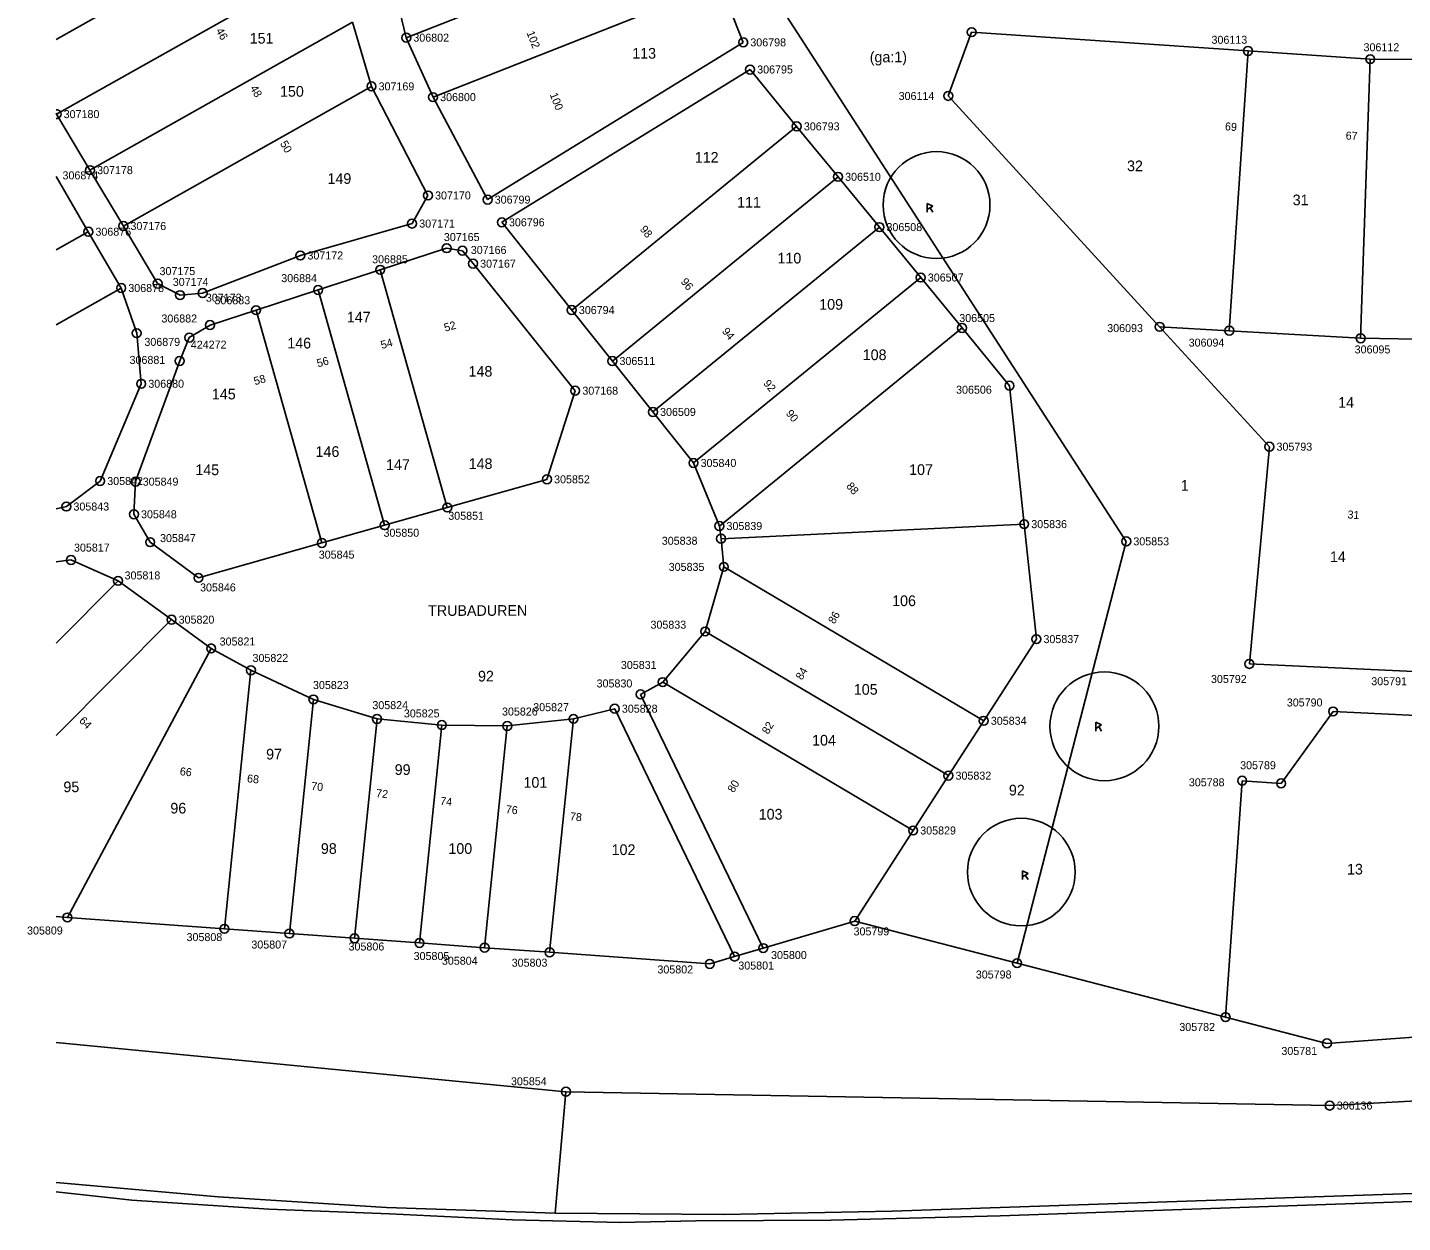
# Model space of a CAD drawing. Extents: x 141995 to 152570, y 6580184 to 6586000.
# Drawn here: x 141996.8 to 142151.4, y 6585355.2 to 6585489.6 of the extents above; entities that cross this region are included whole.
import ezdxf

# ---------------------------------------------------------------- set-up
doc = ezdxf.new("R2010")
doc.units = 0
for name, color, linetype in [('Level 10', 7, 'Continuous'), ('Level 12', 7, 'Continuous'), ('Level 13', 7, 'Continuous'), ('Level 5', 7, 'Continuous'), ('Level 51', 7, 'Continuous'), ('Level 53', 7, 'Continuous'), ('Level 54', 7, 'Continuous'), ('Level 58', 7, 'Continuous'), ('Level 59', 7, 'Continuous'), ('Level 6', 7, 'Continuous'), ('Level 7', 7, 'Continuous')]:
    doc.layers.add(name, color=color, linetype=linetype)

msp = doc.modelspace()

# ---------------------------------------------------------------- linework, layer by layer
at = {"layer": 'Level 10'}
for centre in [(142039.39, 6585488.48), (142077.29, 6585487.95), (142102.98, 6585489.1), (142134.07, 6585486.99), (142078.06, 6585484.89), (142147.81, 6585486.06), (142035.48, 6585483), (142042.4, 6585481.79), (142100.35, 6585481.93), (142083.3, 6585478.5), (142003.81, 6585473.58), (142087.95, 6585472.83), (142041.83, 6585470.73), (142048.54, 6585470.26), (142003.63, 6585466.65), (142007.57, 6585467.29), (142040.04, 6585467.57), (142050.14, 6585467.71), (142092.6, 6585467.17), (142043.93, 6585464.8), (142027.48, 6585463.98), (142045.71, 6585464.52), (142036.46, 6585462.37), (142046.9, 6585463.06), (142007.33, 6585460.32), (142011.43, 6585460.82), (142029.48, 6585460.1), (142097.25, 6585461.5), (142013.95, 6585459.52), (142016.49, 6585459.75), (142022.5, 6585457.83), (142058, 6585457.84), (142017.32, 6585456.15), (142101.9, 6585455.83), (142124.12, 6585455.96), (142131.96, 6585455.52), (142009.07, 6585455.24), (142014.99, 6585454.74), (142146.73, 6585454.67), (142013.91, 6585452.12), (142062.57, 6585452.11), (142009.58, 6585449.55), (142107.24, 6585449.33), (142058.39, 6585448.77), (142067.14, 6585446.38), (142136.47, 6585442.47), (142071.7, 6585440.64), (142004.96, 6585438.61), (142008.95, 6585438.54), (142055.22, 6585438.8), (142001.16, 6585435.74), (142044.01, 6585435.63), (142008.76, 6585434.87), (142108.89, 6585433.76), (142036.96, 6585433.64), (142074.61, 6585433.55), (142010.59, 6585431.73), (142029.9, 6585431.64), (142074.8, 6585432.12), (142120.37, 6585431.82), (142001.68, 6585429.73), (142016.02, 6585427.72), (142075.11, 6585428.96), (142006.98, 6585427.38), (142012.99, 6585423.02), (142073.01, 6585421.69), (142110.26, 6585420.82), (142017.45, 6585419.78), (142021.92, 6585417.32), (142134.22, 6585418.04), (142068.24, 6585415.99), (142028.95, 6585414.04), (142065.74, 6585414.61), (142062.84, 6585413), (142143.64, 6585412.69), (142036.1, 6585411.85), (142043.39, 6585411.16), (142050.75, 6585411.06), (142058.2, 6585411.86), (142104.34, 6585411.64), (142100.37, 6585405.47), (142133.41, 6585404.9), (142137.79, 6585404.6), (142096.4, 6585399.3), (142001.28, 6585389.52), (142089.83, 6585389.11), (142018.94, 6585388.24), (142026.25, 6585387.71), (142033.57, 6585387.18), (142040.88, 6585386.65), (142048.2, 6585386.12), (142079.54, 6585386.07), (142055.51, 6585385.6), (142073.53, 6585384.29), (142076.32, 6585385.12), (142108.09, 6585384.38), (142131.54, 6585378.31), (142142.94, 6585375.36), (142057.35, 6585369.92), (142143.25, 6585368.36)]:
    msp.add_circle(centre, 0.5, dxfattribs=at)
msp.add_arc((142000.06, 6585479.88), 0.5, 263.4159, 96.5841, dxfattribs=at)
at = {"layer": 'Level 12'}
for p, q in [((142097.98, 6585468.84), (142097.98, 6585469.84)), ((142097.98, 6585469.84), (142098.63, 6585469.54)), ((142098.63, 6585469.54), (142097.98, 6585469.14)), ((142098.31, 6585469.34), (142098.63, 6585468.84)), ((142116.94, 6585410.48), (142116.94, 6585411.48)), ((142116.94, 6585411.48), (142117.59, 6585411.18)), ((142117.59, 6585411.18), (142116.94, 6585410.78)), ((142117.27, 6585410.98), (142117.59, 6585410.48)), ((142108.69, 6585393.78), (142108.69, 6585394.78)), ((142108.69, 6585394.78), (142109.34, 6585394.48)), ((142109.34, 6585394.48), (142108.69, 6585394.08)), ((142109.01, 6585394.28), (142109.34, 6585393.78))]:
    msp.add_line(p, q, dxfattribs=at)
for centre, radius in [((142099.03, 6585469.65), 6.01), ((142117.91, 6585411.02), 6.12), ((142108.57, 6585394.62), 6.05)]:
    msp.add_circle(centre, radius, dxfattribs=at)
at = {"layer": 'Level 13'}
for points in [[(142106.18, 6585355.96), (142199.95, 6585359.22), (142280.34, 6585361.53), (142298.3, 6585362.96), (142308.55, 6585364.2), (142315.26, 6585364.94), (142322.71, 6585365.48), (142328.56, 6585365.72), (142332.32, 6585365.37), (142336.72, 6585364.61), (142340.97, 6585363.81), (142343.67, 6585363.75), (142345.72, 6585364.6), (142347.07, 6585365.5), (142347.87, 6585367.45), (142347.76, 6585371.19)], [(142000, 6585358.67), (142008.52, 6585357.72), (142023.93, 6585356.72), (142037.52, 6585356.17), (142051.35, 6585355.52), (142063.46, 6585355.21), (142071.96, 6585355.38), (142087.17, 6585355.46), (142106.18, 6585355.96)]]:
    msp.add_lwpolyline(points, dxfattribs=at)
at = {"layer": 'Level 5'}
for points in [[(142001.28, 6585389.52), (142000, 6585389.61)], [(142018.94, 6585388.24), (142001.28, 6585389.52)], [(142026.25, 6585387.71), (142018.94, 6585388.24)], [(142089.83, 6585389.11), (142079.54, 6585386.07)], [(142108.09, 6585384.38), (142089.83, 6585389.11)], [(142033.57, 6585387.18), (142026.25, 6585387.71)], [(142040.88, 6585386.65), (142033.57, 6585387.18)], [(142048.2, 6585386.12), (142040.88, 6585386.65)], [(142055.51, 6585385.6), (142048.2, 6585386.12)], [(142073.53, 6585384.29), (142055.51, 6585385.6)], [(142076.32, 6585385.12), (142073.53, 6585384.29)], [(142079.54, 6585386.07), (142076.32, 6585385.12)], [(142108.09, 6585384.38), (142131.54, 6585378.31)], [(142142.94, 6585375.36), (142131.54, 6585378.31)], [(142156.85, 6585376.35), (142142.94, 6585375.36)], [(142143.25, 6585368.36), (142295.25, 6585376.5)], [(142000, 6585375.45), (142057.35, 6585369.92)], [(142057.35, 6585369.92), (142143.25, 6585368.36)], [(142094.06, 6585356.49), (142340.21, 6585364.86)], [(142018.24, 6585358.08), (142000, 6585359.72)], [(142037.17, 6585356.91), (142018.24, 6585358.08)], [(142056.13, 6585356.25), (142037.17, 6585356.91)], [(142075.1, 6585356.11), (142056.13, 6585356.25)], [(142094.06, 6585356.49), (142075.1, 6585356.11)]]:
    msp.add_lwpolyline(points, dxfattribs=at)
at = {"layer": 'Level 6'}
msp.add_lwpolyline([(142000, 6585389.61), (142001.28, 6585389.52), (142018.94, 6585388.24), (142026.25, 6585387.71), (142033.57, 6585387.18), (142040.88, 6585386.65), (142048.2, 6585386.12), (142055.51, 6585385.6), (142073.53, 6585384.29), (142076.32, 6585385.12), (142079.54, 6585386.07), (142089.83, 6585389.11), (142108.09, 6585384.38), (142131.54, 6585378.31), (142142.94, 6585375.36), (142156.85, 6585376.35)], dxfattribs=at)
at = {"layer": 'Level 7'}
for points in [[(142066.65, 6585514.98), (142120.37, 6585431.82)], [(142000, 6585488.26), (142028.3, 6585504.2)], [(142039.39, 6585488.48), (142072.02, 6585501.34)], [(142000.06, 6585479.88), (142031.24, 6585497.44)], [(142037.64, 6585495.67), (142039.39, 6585488.48)], [(142042.4, 6585481.79), (142074.71, 6585494.52)], [(142077.29, 6585487.95), (142074.71, 6585494.52)], [(142003.81, 6585473.58), (142033.36, 6585490.22)], [(142033.36, 6585490.22), (142035.48, 6585483)], [(142039.39, 6585488.48), (142042.4, 6585481.79)], [(142100.35, 6585481.93), (142102.98, 6585489.1)], [(142102.98, 6585489.1), (142134.07, 6585486.99)], [(142048.54, 6585470.26), (142077.29, 6585487.95)], [(142131.96, 6585455.52), (142134.07, 6585486.99)], [(142134.07, 6585486.99), (142147.81, 6585486.06)], [(142146.73, 6585454.67), (142147.81, 6585486.06)], [(142147.81, 6585486.06), (142161.52, 6585485.99)], [(142078.06, 6585484.89), (142050.14, 6585467.71)], [(142083.3, 6585478.5), (142078.06, 6585484.89)], [(142007.57, 6585467.29), (142035.48, 6585483)], [(142035.48, 6585483), (142041.83, 6585470.73)], [(142042.4, 6585481.79), (142048.54, 6585470.26)], [(142124.12, 6585455.96), (142100.35, 6585481.93)], [(142000.06, 6585479.88), (142000, 6585479.98)], [(142003.81, 6585473.58), (142000.06, 6585479.88)], [(142058, 6585457.84), (142083.3, 6585478.5)], [(142087.95, 6585472.83), (142083.3, 6585478.5)], [(142007.57, 6585467.29), (142003.81, 6585473.58)], [(142000, 6585472.87), (142003.63, 6585466.65)], [(142062.57, 6585452.11), (142087.95, 6585472.83)], [(142092.6, 6585467.17), (142087.95, 6585472.83)], [(142041.83, 6585470.73), (142040.04, 6585467.57)], [(142011.43, 6585460.82), (142007.57, 6585467.29)], [(142040.04, 6585467.57), (142027.48, 6585463.98)], [(142050.14, 6585467.71), (142058, 6585457.84)], [(142067.14, 6585446.38), (142092.6, 6585467.17)], [(142092.6, 6585467.17), (142097.25, 6585461.5)], [(142003.63, 6585466.65), (142000, 6585464.6)], [(142003.63, 6585466.65), (142007.33, 6585460.32)], [(142027.48, 6585463.98), (142016.49, 6585459.75)], [(142036.46, 6585462.37), (142043.93, 6585464.8)], [(142043.93, 6585464.8), (142045.71, 6585464.52)], [(142045.71, 6585464.52), (142046.9, 6585463.06)], [(142029.48, 6585460.1), (142036.46, 6585462.37)], [(142036.46, 6585462.37), (142044.01, 6585435.63)], [(142046.9, 6585463.06), (142058.39, 6585448.77)], [(142013.95, 6585459.52), (142011.43, 6585460.82)], [(142097.25, 6585461.5), (142071.7, 6585440.64)], [(142101.9, 6585455.83), (142097.25, 6585461.5)], [(142007.33, 6585460.32), (142000, 6585456.18)], [(142007.33, 6585460.32), (142009.07, 6585455.24)], [(142016.49, 6585459.75), (142013.95, 6585459.52)], [(142022.5, 6585457.83), (142029.48, 6585460.1)], [(142029.48, 6585460.1), (142036.96, 6585433.64)], [(142017.32, 6585456.15), (142022.5, 6585457.83)], [(142022.5, 6585457.83), (142029.9, 6585431.64)], [(142058, 6585457.84), (142062.57, 6585452.11)], [(142014.99, 6585454.74), (142017.32, 6585456.15)], [(142124.12, 6585455.96), (142131.96, 6585455.52)], [(142124.12, 6585455.96), (142136.47, 6585442.47)], [(142009.07, 6585455.24), (142009.58, 6585449.55)], [(142013.91, 6585452.12), (142014.99, 6585454.74)], [(142101.9, 6585455.83), (142074.61, 6585433.55)], [(142101.9, 6585455.83), (142107.24, 6585449.33)], [(142131.96, 6585455.52), (142146.73, 6585454.67)], [(142146.73, 6585454.67), (142155.21, 6585454.53)], [(142013.91, 6585452.12), (142008.95, 6585438.54)], [(142062.57, 6585452.11), (142067.14, 6585446.38)], [(142009.58, 6585449.55), (142004.96, 6585438.61)], [(142058.39, 6585448.77), (142055.22, 6585438.8)], [(142107.24, 6585449.33), (142108.89, 6585433.76)], [(142067.14, 6585446.38), (142071.7, 6585440.64)], [(142134.22, 6585418.04), (142136.47, 6585442.47)], [(142071.7, 6585440.64), (142074.61, 6585433.55)], [(142004.96, 6585438.61), (142001.16, 6585435.74)], [(142008.76, 6585434.87), (142008.95, 6585438.54)], [(142055.22, 6585438.8), (142044.01, 6585435.63)], [(142001.16, 6585435.74), (142000, 6585435.47)], [(142010.59, 6585431.73), (142008.76, 6585434.87)], [(142044.01, 6585435.63), (142036.96, 6585433.64)], [(142036.96, 6585433.64), (142029.9, 6585431.64)], [(142074.8, 6585432.12), (142074.61, 6585433.55)], [(142108.89, 6585433.76), (142074.8, 6585432.12)], [(142110.26, 6585420.82), (142108.89, 6585433.76)], [(142016.02, 6585427.72), (142010.59, 6585431.73)], [(142029.9, 6585431.64), (142016.02, 6585427.72)], [(142074.8, 6585432.12), (142075.11, 6585428.96)], [(142120.37, 6585431.82), (142108.09, 6585384.38)], [(142001.68, 6585429.73), (142000, 6585429.52)], [(142006.98, 6585427.38), (142001.68, 6585429.73)], [(142075.11, 6585428.96), (142073.01, 6585421.69)], [(142075.11, 6585428.96), (142104.34, 6585411.64)], [(142006.98, 6585427.38), (142000, 6585420.38)], [(142012.99, 6585423.02), (142006.98, 6585427.38)], [(142012.99, 6585423.02), (142000, 6585410)], [(142017.45, 6585419.78), (142012.99, 6585423.02)], [(142073.01, 6585421.69), (142068.24, 6585415.99)], [(142073.01, 6585421.69), (142100.37, 6585405.47)], [(142104.34, 6585411.64), (142110.26, 6585420.82)], [(142017.45, 6585419.78), (142001.28, 6585389.52)], [(142021.92, 6585417.32), (142017.45, 6585419.78)], [(142021.92, 6585417.32), (142018.94, 6585388.24)], [(142028.95, 6585414.04), (142021.92, 6585417.32)], [(142152.7, 6585417.19), (142134.22, 6585418.04)], [(142068.24, 6585415.99), (142065.74, 6585414.61)], [(142068.24, 6585415.99), (142096.4, 6585399.3)], [(142065.74, 6585414.61), (142079.54, 6585386.07)], [(142028.95, 6585414.04), (142026.25, 6585387.71)], [(142036.1, 6585411.85), (142028.95, 6585414.04)], [(142062.84, 6585413), (142058.2, 6585411.86)], [(142076.32, 6585385.12), (142062.84, 6585413)], [(142137.79, 6585404.6), (142143.64, 6585412.69)], [(142143.64, 6585412.69), (142159.2, 6585411.93)], [(142036.1, 6585411.85), (142033.57, 6585387.18)], [(142043.39, 6585411.16), (142036.1, 6585411.85)], [(142043.39, 6585411.16), (142040.88, 6585386.65)], [(142050.75, 6585411.06), (142043.39, 6585411.16)], [(142050.75, 6585411.06), (142048.2, 6585386.12)], [(142058.2, 6585411.86), (142050.75, 6585411.06)], [(142058.2, 6585411.86), (142055.51, 6585385.6)], [(142100.37, 6585405.47), (142104.34, 6585411.64)], [(142096.4, 6585399.3), (142100.37, 6585405.47)], [(142131.54, 6585378.31), (142133.41, 6585404.9)], [(142133.41, 6585404.9), (142137.79, 6585404.6)], [(142089.83, 6585389.11), (142096.4, 6585399.3)], [(142057.35, 6585369.92), (142056.13, 6585356.25)]]:
    msp.add_lwpolyline(points, dxfattribs=at)

# ---------------------------------------------------------------- texts
at = {"layer": 'Level 51'}
for s, rotation, p in [('151', 0.0527, (142021.78, 6585487.81)), ('113', 0.0527, (142064.81, 6585486.12)), ('(ga:1)', 0.0527, (142091.52, 6585485.71)), ('150', 0.0527, (142025.19, 6585481.84)), ('112', 0.0527, (142071.84, 6585474.42)), ('32', 0.0527, (142120.46, 6585473.46)), ('149', 0.0527, (142030.53, 6585472.03)), ('111', 0.0527, (142076.6, 6585469.36)), ('31', 0.0527, (142139.09, 6585469.63)), ('110', 0.0527, (142081.14, 6585463.08)), ('109', 0.0527, (142085.84, 6585457.88)), ('147', 0.0527, (142032.71, 6585456.45)), ('108', 0.0527, (142090.73, 6585452.21)), ('148', 0.0527, (142046.4, 6585450.35)), ('146', 0.0527, (142029.19, 6585441.32)), ('145', 0.0527, (142015.67, 6585439.27)), ('107', 0.0527, (142095.95, 6585439.29)), ('1', 0.0527, (142126.51, 6585437.52)), ('14', 0.0527, (142143.28, 6585429.49)), ('106', 0.0527, (142094.04, 6585424.54)), ('105', 0.0526, (142089.73, 6585414.57)), ('104', 0.0526, (142085.04, 6585408.85)), ('97', 0.0526, (142023.63, 6585407.29)), ('99', 0.0526, (142038.09, 6585405.55)), ('101', 0.0526, (142052.58, 6585404.11)), ('95', 0.0526, (142000.83, 6585403.61)), ('96', 0.0526, (142012.86, 6585401.21)), ('103', 0.0526, (142079.03, 6585400.53)), ('98', 0.0526, (142029.79, 6585396.67)), ('100', 0.0526, (142044.13, 6585396.67)), ('102', 0.0526, (142062.49, 6585396.54)), ('13', 0.0526, (142145.2, 6585394.35))]:
    msp.add_text(s, height=1.2, rotation=rotation, dxfattribs=at).set_placement(p)
at = {"layer": 'Level 53'}
for s, rotation, p in [('306802', 0.0527, (142040.19, 6585488.03)), ('306798', 0.0527, (142078.09, 6585487.5)), ('306113', 0.0527, (142129.96, 6585487.79)), ('306112', 0.0527, (142147.06, 6585486.95)), ('306795', 0.0527, (142078.86, 6585484.45)), ('307169', 0.0527, (142036.28, 6585482.55)), ('306800', 0.0527, (142043.2, 6585481.34)), ('306114', 0.0527, (142094.77, 6585481.47)), ('307180', 0.0527, (142000.86, 6585479.43)), ('306793', 0.0527, (142084.11, 6585478.05)), ('306874', 0.0527, (142000.73, 6585472.54)), ('307178', 0.0527, (142004.62, 6585473.13)), ('306510', 0.0527, (142088.75, 6585472.38)), ('307170', 0.0527, (142042.63, 6585470.28)), ('306799', 0.0527, (142049.34, 6585469.81)), ('306876', 0.0527, (142004.43, 6585466.2)), ('307176', 0.0527, (142008.37, 6585466.84)), ('307171', 0.0527, (142040.85, 6585467.12)), ('306796', 0.0527, (142050.94, 6585467.26)), ('306508', 0.0527, (142093.4, 6585466.72)), ('307165', 0.0527, (142043.62, 6585465.6)), ('307172', 0.0527, (142028.28, 6585463.53)), ('306885', 0.0527, (142035.55, 6585463.1)), ('307166', 0.0527, (142046.65, 6585464.15)), ('307175', 0.0527, (142011.64, 6585461.77)), ('307167', 0.0527, (142047.7, 6585462.61)), ('306878', 0.0527, (142008.13, 6585459.87)), ('307174', 0.0527, (142013.13, 6585460.55)), ('306884', 0.0527, (142025.33, 6585460.98)), ('306507', 0.0527, (142098.05, 6585461.05)), ('307173', 0.0527, (142016.85, 6585458.78)), ('306883', 0.0527, (142017.82, 6585458.49)), ('306794', 0.0527, (142058.8, 6585457.39)), ('306882', 0.0527, (142011.85, 6585456.44)), ('306505', 0.0527, (142101.59, 6585456.49)), ('306093', 0.0527, (142118.23, 6585455.36)), ('306879', 0.0527, (142009.94, 6585453.81)), ('424272', 0.0527, (142015.16, 6585453.5)), ('306094', 0.0527, (142127.39, 6585453.73)), ('306095', 0.0527, (142146.06, 6585452.96)), ('306881', 0.0527, (142008.27, 6585451.78)), ('306511', 0.0527, (142063.37, 6585451.66)), ('306880', 0.0527, (142010.38, 6585449.1)), ('307168', 0.0527, (142059.2, 6585448.32)), ('306506', 0.0527, (142101.23, 6585448.43)), ('306509', 0.0527, (142067.94, 6585445.93)), ('305793', 0.0527, (142137.27, 6585442.02)), ('305840', 0.0527, (142072.5, 6585440.19)), ('305842', 0.0527, (142005.76, 6585438.16)), ('305849', 0.0527, (142009.75, 6585438.09)), ('305852', 0.0527, (142056.02, 6585438.35)), ('305843', 0.0527, (142001.96, 6585435.29)), ('305848', 0.0527, (142009.56, 6585434.42)), ('305851', 0.0527, (142044.12, 6585434.25)), ('305850', 0.0527, (142036.83, 6585432.34)), ('305839', 0.0527, (142075.41, 6585433.1)), ('305836', 0.0527, (142109.69, 6585433.31)), ('305817', 0.0527, (142002.02, 6585430.67)), ('305847', 0.0527, (142011.7, 6585431.74)), ('305838', 0.0527, (142068.13, 6585431.44)), ('305853', 0.0527, (142121.17, 6585431.37)), ('305845', 0.0527, (142029.55, 6585429.88)), ('305818', 0.0527, (142007.71, 6585427.54)), ('305835', 0.0527, (142068.91, 6585428.5)), ('305846', 0.0527, (142016.2, 6585426.19)), ('305820', 0.0527, (142013.79, 6585422.57)), ('305833', 0.0527, (142066.86, 6585422)), ('305821', 0.0526, (142018.4, 6585420.11)), ('305837', 0.0527, (142111.06, 6585420.38)), ('305822', 0.0526, (142022.1, 6585418.26)), ('305831', 0.0526, (142063.53, 6585417.47)), ('305823', 0.0526, (142028.9, 6585415.21)), ('305830', 0.0526, (142060.8, 6585415.39)), ('305792', 0.0527, (142129.9, 6585415.89)), ('305791', 0.0527, (142147.93, 6585415.64)), ('305790', 0.0526, (142138.43, 6585413.25)), ('305824', 0.0526, (142035.58, 6585412.95)), ('305825', 0.0526, (142039.12, 6585412.02)), ('305826', 0.0526, (142050.16, 6585412.23)), ('305827', 0.0526, (142053.67, 6585412.72)), ('305828', 0.0526, (142063.64, 6585412.55)), ('305834', 0.0526, (142105.14, 6585411.19)), ('305789', 0.0526, (142133.18, 6585406.19)), ('305832', 0.0526, (142101.17, 6585405.02)), ('305788', 0.0526, (142127.41, 6585404.27)), ('305829', 0.0526, (142097.2, 6585398.85)), ('305809', 0.0526, (141996.74, 6585387.6)), ('305799', 0.0526, (142089.7, 6585387.5)), ('305808', 0.0526, (142014.68, 6585386.86)), ('305807', 0.0526, (142021.97, 6585386.02)), ('305806', 0.0526, (142032.9, 6585385.8)), ('305805', 0.0526, (142040.22, 6585384.73)), ('305804', 0.0526, (142043.4, 6585384.2)), ('305803', 0.0526, (142051.25, 6585383.98)), ('305800', 0.0526, (142080.42, 6585384.84)), ('305802', 0.0526, (142067.64, 6585383.22)), ('305801', 0.0526, (142076.74, 6585383.66)), ('305798', 0.0526, (142103.45, 6585382.65)), ('305782', 0.0526, (142126.34, 6585376.75)), ('305781', 0.0526, (142137.82, 6585374.05)), ('305854', 0.0526, (142051.17, 6585370.64)), ('306136', 0.0526, (142144.05, 6585367.91))]:
    msp.add_text(s, height=0.9, rotation=rotation, dxfattribs=at).set_placement(p)
at = {"layer": 'Level 54'}
for s, rotation, p in [('46', 299.4248, (142017.94, 6585489.27)), ('102', 291.4636, (142052.9, 6585489.04)), ('48', 299.4248, (142021.79, 6585482.82)), ('100', 291.4636, (142055.51, 6585482.09)), ('69', 355.8187, (142131.45, 6585478.07)), ('67', 358.0647, (142145.04, 6585477.02)), ('50', 299.4248, (142025.16, 6585476.58)), ('98', 309.3702, (142065.61, 6585466.9)), ('96', 309.3702, (142070.21, 6585461)), ('52', 15.7626, (142043.78, 6585455.4)), ('54', 15.7626, (142036.66, 6585453.45)), ('94', 309.3702, (142074.85, 6585455.42)), ('56', 15.7626, (142029.47, 6585451.39)), ('58', 15.7626, (142022.38, 6585449.38)), ('92', 309.3702, (142079.5, 6585449.56)), ('90', 309.3722, (142082.03, 6585446.18)), ('88', 309.3722, (142088.82, 6585438.02)), ('31', 356.1207, (142145.23, 6585434.41)), ('86', 59.346, (142087.54, 6585422.46)), ('84', 59.347, (142083.9, 6585416.15)), ('64', 314.9564, (142002.53, 6585411.58)), ('82', 59.347, (142080.1, 6585410.05)), ('66', 353.7837, (142013.89, 6585405.53)), ('68', 353.7837, (142021.45, 6585404.73)), ('80', 59.347, (142076.23, 6585403.48)), ('70', 353.7837, (142028.66, 6585403.87)), ('72', 353.7837, (142035.96, 6585403.07)), ('74', 353.7837, (142043.17, 6585402.2)), ('76', 353.7837, (142050.55, 6585401.26)), ('78', 353.7837, (142057.76, 6585400.47))]:
    msp.add_text(s, height=0.9, rotation=rotation, dxfattribs=at).set_placement(p)
at = {"layer": 'Level 58'}
msp.add_text('TRUBADUREN', height=1.2, rotation=0.0527, dxfattribs=at).set_placement((142041.85, 6585423.44))
at = {"layer": 'Level 59'}
for s, rotation, p in [('146', 0.0527, (142026.01, 6585453.52)), ('145', 0.0527, (142017.53, 6585447.79)), ('14', 0.0527, (142144.21, 6585446.85)), ('147', 0.0527, (142037.12, 6585439.85)), ('148', 0.0527, (142046.41, 6585439.96)), ('92', 0.0526, (142047.46, 6585416.06)), ('92', 0.0526, (142107.17, 6585403.24))]:
    msp.add_text(s, height=1.2, rotation=rotation, dxfattribs=at).set_placement(p)

doc.saveas('drawing.dxf')
